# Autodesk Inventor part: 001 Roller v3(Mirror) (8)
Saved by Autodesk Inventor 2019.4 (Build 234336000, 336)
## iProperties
Created: 2020-06
Part Number: 001 Roller v3(Mirror) (8)
Material: Generic
Document SubType Name: Modeling
Designer: Administrator
Density: 1 g/cm^3
Appearance: Default
Title: 001 Roller v3(Mirror) (8)
Author: Administrator
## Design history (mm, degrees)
